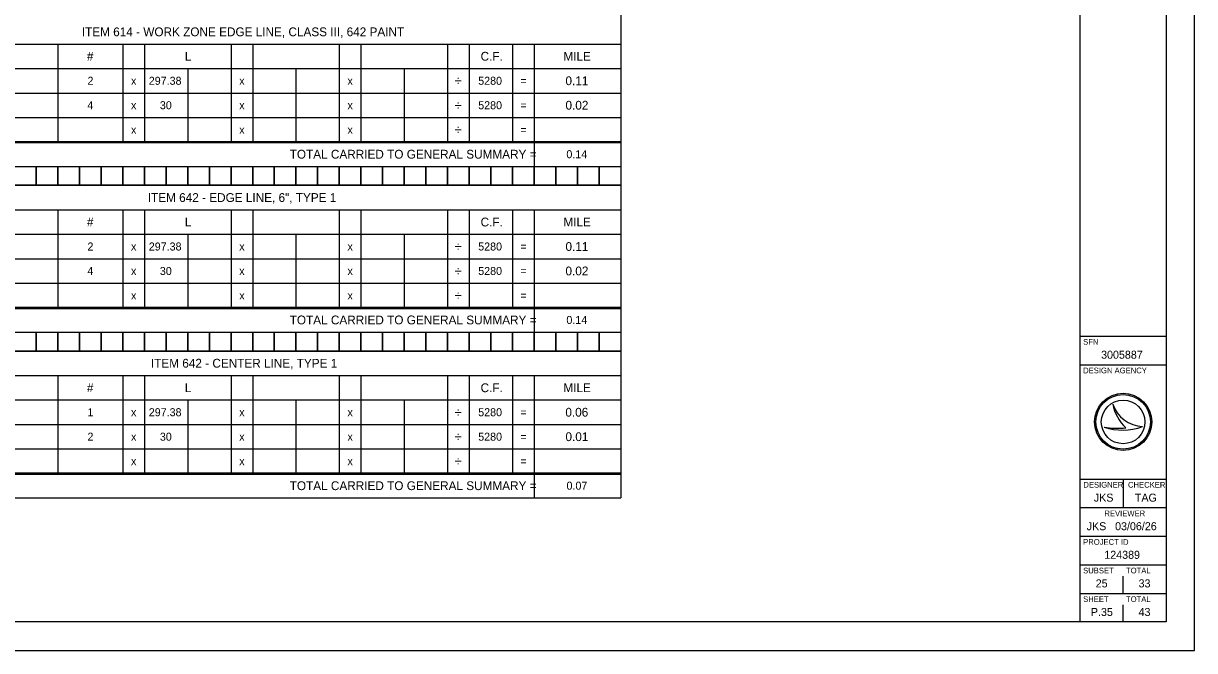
# Model space of a CAD drawing. Extents: x 0 to 34, y 0 to 22.
# Drawn here: x 13.51 to 34, y 0 to 10.97 of the extents above; entities that cross this region are included whole.
import ezdxf

# ---------------------------------------------------------------- set-up
doc = ezdxf.new("R2010")
doc.units = 0
for name, color, linetype in [('Default', 7, 'Continuous'), ('SH_Border', 7, 'Continuous'), ('SH_Cut_Line', 7, 'Continuous'), ('SH_Data', 7, 'Continuous')]:
    doc.layers.add(name, color=color, linetype=linetype)

msp = doc.modelspace()

# ---------------------------------------------------------------- linework, layer by layer
at = {"layer": 'Default'}
for p, q in [((23.957, 11.806), (23.957, 8.885)), ((10.698, 10.609), (23.957, 10.609)), ((14.107, 10.609), (14.107, 8.907)), ((15.244, 10.609), (15.244, 8.907)), ((15.622, 10.609), (15.622, 8.907)), ((17.138, 10.609), (17.138, 8.907)), ((17.517, 10.609), (17.517, 8.907)), ((19.032, 10.609), (19.032, 8.907)), ((19.411, 10.609), (19.411, 8.907)), ((20.926, 10.609), (20.926, 8.907)), ((21.305, 10.609), (21.305, 8.907)), ((22.062, 10.609), (22.062, 8.907)), ((22.441, 10.609), (22.441, 8.907)), ((10.698, 10.181), (23.957, 10.181)), ((16.38, 10.181), (16.38, 8.907)), ((18.274, 10.181), (18.274, 8.907)), ((20.168, 10.181), (20.168, 8.907)), ((10.698, 9.753), (23.957, 9.753)), ((10.698, 9.324), (23.957, 9.324)), ((10.698, 8.907), (23.957, 8.907)), ((10.698, 8.885), (23.957, 8.885)), ((22.441, 8.885), (22.441, 8.468)), ((23.957, 8.907), (23.957, 5.986)), ((10.698, 8.468), (23.957, 8.468)), ((10.698, 8.139), (23.957, 8.139)), ((10.698, 7.71), (23.957, 7.71)), ((14.107, 7.71), (14.107, 6.008)), ((15.244, 7.71), (15.244, 6.008)), ((15.622, 7.71), (15.622, 6.008)), ((17.138, 7.71), (17.138, 6.008)), ((17.517, 7.71), (17.517, 6.008)), ((19.032, 7.71), (19.032, 6.008)), ((19.411, 7.71), (19.411, 6.008)), ((20.926, 7.71), (20.926, 6.008)), ((21.305, 7.71), (21.305, 6.008)), ((22.062, 7.71), (22.062, 6.008)), ((22.441, 7.71), (22.441, 6.008)), ((10.698, 7.282), (23.957, 7.282)), ((16.38, 7.282), (16.38, 6.008)), ((18.274, 7.282), (18.274, 6.008)), ((20.168, 7.282), (20.168, 6.008)), ((10.698, 6.854), (23.957, 6.854)), ((10.698, 6.426), (23.957, 6.426)), ((10.698, 6.008), (23.957, 6.008)), ((10.698, 5.986), (23.957, 5.986)), ((22.441, 5.986), (22.441, 5.569)), ((23.957, 6.008), (23.957, 3.088)), ((10.698, 5.569), (23.957, 5.569)), ((10.698, 5.24), (23.957, 5.24)), ((10.698, 4.811), (23.957, 4.811)), ((14.107, 4.811), (14.107, 3.109)), ((15.244, 4.811), (15.244, 3.109)), ((15.622, 4.811), (15.622, 3.109)), ((17.138, 4.811), (17.138, 3.109)), ((17.517, 4.811), (17.517, 3.109)), ((19.032, 4.811), (19.032, 3.109)), ((19.411, 4.811), (19.411, 3.109)), ((20.926, 4.811), (20.926, 3.109)), ((21.305, 4.811), (21.305, 3.109)), ((22.062, 4.811), (22.062, 3.109)), ((22.441, 4.811), (22.441, 3.109)), ((10.698, 4.383), (23.957, 4.383)), ((16.38, 4.383), (16.38, 3.109)), ((18.274, 4.383), (18.274, 3.109)), ((20.168, 4.383), (20.168, 3.109)), ((10.698, 3.955), (23.957, 3.955)), ((10.698, 3.527), (23.957, 3.527)), ((10.698, 3.109), (23.957, 3.109)), ((10.698, 3.088), (23.957, 3.088)), ((22.441, 3.088), (22.441, 2.67)), ((23.957, 3.109), (23.957, 2.67)), ((10.698, 2.67), (23.957, 2.67))]:
    msp.add_line(p, q, dxfattribs=at)
for points in [[(13.35, 8.468), (13.728, 8.468), (13.728, 8.139), (13.35, 8.139)], [(13.728, 8.468), (14.107, 8.468), (14.107, 8.139), (13.728, 8.139)], [(14.107, 8.468), (14.486, 8.468), (14.486, 8.139), (14.107, 8.139)], [(14.486, 8.468), (14.865, 8.468), (14.865, 8.139), (14.486, 8.139)], [(14.865, 8.468), (15.244, 8.468), (15.244, 8.139), (14.865, 8.139)], [(15.244, 8.468), (15.622, 8.468), (15.622, 8.139), (15.244, 8.139)], [(15.622, 8.468), (16.001, 8.468), (16.001, 8.139), (15.622, 8.139)], [(16.001, 8.468), (16.38, 8.468), (16.38, 8.139), (16.001, 8.139)], [(16.38, 8.468), (16.759, 8.468), (16.759, 8.139), (16.38, 8.139)], [(16.759, 8.468), (17.138, 8.468), (17.138, 8.139), (16.759, 8.139)], [(17.138, 8.468), (17.517, 8.468), (17.517, 8.139), (17.138, 8.139)], [(17.517, 8.468), (17.895, 8.468), (17.895, 8.139), (17.517, 8.139)], [(17.895, 8.468), (18.274, 8.468), (18.274, 8.139), (17.895, 8.139)], [(18.274, 8.468), (18.653, 8.468), (18.653, 8.139), (18.274, 8.139)], [(18.653, 8.468), (19.032, 8.468), (19.032, 8.139), (18.653, 8.139)], [(19.032, 8.468), (19.411, 8.468), (19.411, 8.139), (19.032, 8.139)], [(19.411, 8.468), (19.79, 8.468), (19.79, 8.139), (19.411, 8.139)], [(19.79, 8.468), (20.168, 8.468), (20.168, 8.139), (19.79, 8.139)], [(20.168, 8.468), (20.547, 8.468), (20.547, 8.139), (20.168, 8.139)], [(20.547, 8.468), (20.926, 8.468), (20.926, 8.139), (20.547, 8.139)], [(20.926, 8.468), (21.305, 8.468), (21.305, 8.139), (20.926, 8.139)], [(21.305, 8.468), (21.684, 8.468), (21.684, 8.139), (21.305, 8.139)], [(21.684, 8.468), (22.062, 8.468), (22.062, 8.139), (21.684, 8.139)], [(22.062, 8.468), (22.441, 8.468), (22.441, 8.139), (22.062, 8.139)], [(22.441, 8.468), (22.82, 8.468), (22.82, 8.139), (22.441, 8.139)], [(22.82, 8.468), (23.199, 8.468), (23.199, 8.139), (22.82, 8.139)], [(23.199, 8.468), (23.578, 8.468), (23.578, 8.139), (23.199, 8.139)], [(23.578, 8.468), (23.957, 8.468), (23.957, 8.139), (23.578, 8.139)], [(13.35, 5.569), (13.728, 5.569), (13.728, 5.24), (13.35, 5.24)], [(13.728, 5.569), (14.107, 5.569), (14.107, 5.24), (13.728, 5.24)], [(14.107, 5.569), (14.486, 5.569), (14.486, 5.24), (14.107, 5.24)], [(14.486, 5.569), (14.865, 5.569), (14.865, 5.24), (14.486, 5.24)], [(14.865, 5.569), (15.244, 5.569), (15.244, 5.24), (14.865, 5.24)], [(15.244, 5.569), (15.622, 5.569), (15.622, 5.24), (15.244, 5.24)], [(15.622, 5.569), (16.001, 5.569), (16.001, 5.24), (15.622, 5.24)], [(16.001, 5.569), (16.38, 5.569), (16.38, 5.24), (16.001, 5.24)], [(16.38, 5.569), (16.759, 5.569), (16.759, 5.24), (16.38, 5.24)], [(16.759, 5.569), (17.138, 5.569), (17.138, 5.24), (16.759, 5.24)], [(17.138, 5.569), (17.517, 5.569), (17.517, 5.24), (17.138, 5.24)], [(17.517, 5.569), (17.895, 5.569), (17.895, 5.24), (17.517, 5.24)], [(17.895, 5.569), (18.274, 5.569), (18.274, 5.24), (17.895, 5.24)], [(18.274, 5.569), (18.653, 5.569), (18.653, 5.24), (18.274, 5.24)], [(18.653, 5.569), (19.032, 5.569), (19.032, 5.24), (18.653, 5.24)], [(19.032, 5.569), (19.411, 5.569), (19.411, 5.24), (19.032, 5.24)], [(19.411, 5.569), (19.79, 5.569), (19.79, 5.24), (19.411, 5.24)], [(19.79, 5.569), (20.168, 5.569), (20.168, 5.24), (19.79, 5.24)], [(20.168, 5.569), (20.547, 5.569), (20.547, 5.24), (20.168, 5.24)], [(20.547, 5.569), (20.926, 5.569), (20.926, 5.24), (20.547, 5.24)], [(20.926, 5.569), (21.305, 5.569), (21.305, 5.24), (20.926, 5.24)], [(21.305, 5.569), (21.684, 5.569), (21.684, 5.24), (21.305, 5.24)], [(21.684, 5.569), (22.062, 5.569), (22.062, 5.24), (21.684, 5.24)], [(22.062, 5.569), (22.441, 5.569), (22.441, 5.24), (22.062, 5.24)], [(22.441, 5.569), (22.82, 5.569), (22.82, 5.24), (22.441, 5.24)], [(22.82, 5.569), (23.199, 5.569), (23.199, 5.24), (22.82, 5.24)], [(23.199, 5.569), (23.578, 5.569), (23.578, 5.24), (23.199, 5.24)], [(23.578, 5.569), (23.957, 5.569), (23.957, 5.24), (23.578, 5.24)]]:
    msp.add_lwpolyline(points, close=True, dxfattribs=at)
at = {"layer": 'SH_Border'}
for p, q in [((32, 0.5), (32, 21.5)), ((32, 5.5), (33.5, 5.5)), ((32, 5), (33.5, 5)), ((32, 3), (33.5, 3)), ((32.75, 3), (32.75, 2.5)), ((32, 2.5), (33.5, 2.5)), ((32, 2), (33.5, 2)), ((32, 1.5), (33.5, 1.5)), ((32, 1), (33.5, 1))]:
    msp.add_line(p, q, dxfattribs=at)
msp.add_lwpolyline([(1.5, 21.5), (33.5, 21.5), (33.5, 0.5), (1.5, 0.5)], close=True, dxfattribs=at)
at = {"layer": 'SH_Cut_Line'}
msp.add_lwpolyline([(0, 0), (34, 0), (34, 22), (0, 22)], close=True, dxfattribs=at)
at = {"layer": 'SH_Data'}
for p, q in [((32.567, 4.31), (32.567, 4.31)), ((32.417, 3.91), (32.417, 3.91)), ((32.75, 4), (32.75, 4)), ((33.087, 3.919), (33.087, 3.919)), ((32.75, 1), (32.75, 1.3)), ((32.375, 0.675), (32.375, 0.675)), ((32.75, 0.5), (32.75, 0.8))]:
    msp.add_line(p, q, dxfattribs=at)
for radius in [0.5, 0.477, 0.477, 0.382]:
    msp.add_circle((32.75, 4), radius, dxfattribs=at)
for centre, radius, start, end in [((33.116, 4.498), 0.58, 198.9257, 198.9319), ((33.347, 4.47), 0.796, 191.6379, 191.6421), ((33.116, 4.498), 0.58, 198.9319, 267.1657), ((33.347, 4.47), 0.796, 191.6421, 226.0947), ((32.739, 4.87), 1.013, 251.4576, 290.0832), ((32.648, 5.154), 1.266, 259.4964, 259.4995), ((32.739, 4.87), 1.013, 251.4527, 251.4576), ((32.648, 5.154), 1.266, 259.4995, 276.6672)]:
    msp.add_arc(centre, radius, start, end, dxfattribs=at)

# ---------------------------------------------------------------- texts
at = {"layer": 'Default'}
for s, height, p in [('ITEM 614 - WORK ZONE EDGE LINE, CLASS III, 642 PAINT', 0.154, (14.527, 10.746)), ('#', 0.154, (14.617, 10.318)), ('L', 0.154, (16.33, 10.318)), ('C.F.', 0.154, (21.506, 10.318)), ('MILE', 0.154, (22.955, 10.318)), ('0.11', 0.154, (22.991, 9.89)), ('2', 0.14, (14.626, 9.897)), ('x', 0.14, (15.388, 9.897)), ('297.38', 0.14, (15.699, 9.897)), ('x', 0.14, (17.282, 9.897)), ('x', 0.14, (19.176, 9.897)), ('÷', 0.168, (21.053, 9.883)), ('5280', 0.14, (21.464, 9.897)), ('=', 0.14, (22.202, 9.897)), ('4', 0.14, (14.623, 9.469)), ('x', 0.14, (15.388, 9.469)), ('30', 0.14, (15.893, 9.469)), ('x', 0.14, (17.282, 9.469)), ('x', 0.14, (19.176, 9.469)), ('÷', 0.168, (21.053, 9.455)), ('5280', 0.14, (21.464, 9.469)), ('=', 0.14, (22.202, 9.469)), ('0.02', 0.154, (22.991, 9.462)), ('x', 0.14, (15.388, 9.04)), ('x', 0.14, (17.282, 9.04)), ('x', 0.14, (19.176, 9.04)), ('÷', 0.168, (21.053, 9.026)), ('=', 0.14, (22.202, 9.04)), ('TOTAL CARRIED TO GENERAL SUMMARY =', 0.154, (18.165, 8.605)), ('0.14', 0.14, (23.007, 8.612)), ('ITEM 642 - EDGE LINE, 6", TYPE 1', 0.154, (15.681, 7.847)), ('#', 0.154, (14.617, 7.419)), ('L', 0.154, (16.33, 7.419)), ('C.F.', 0.154, (21.506, 7.419)), ('MILE', 0.154, (22.955, 7.419)), ('2', 0.14, (14.626, 6.998)), ('x', 0.14, (15.388, 6.998)), ('297.38', 0.14, (15.699, 6.998)), ('x', 0.14, (17.282, 6.998)), ('x', 0.14, (19.176, 6.998)), ('÷', 0.168, (21.053, 6.984)), ('5280', 0.14, (21.464, 6.998)), ('=', 0.14, (22.202, 6.998)), ('0.11', 0.154, (22.991, 6.991)), ('4', 0.14, (14.623, 6.57)), ('x', 0.14, (15.388, 6.57)), ('30', 0.14, (15.893, 6.57)), ('x', 0.14, (17.282, 6.57)), ('x', 0.14, (19.176, 6.57)), ('÷', 0.168, (21.053, 6.556)), ('5280', 0.14, (21.464, 6.57)), ('=', 0.14, (22.202, 6.57)), ('0.02', 0.154, (22.991, 6.563)), ('x', 0.14, (15.388, 6.141)), ('x', 0.14, (17.282, 6.141)), ('x', 0.14, (19.176, 6.141)), ('÷', 0.168, (21.053, 6.127)), ('=', 0.14, (22.202, 6.141)), ('TOTAL CARRIED TO GENERAL SUMMARY =', 0.154, (18.165, 5.706)), ('0.14', 0.14, (23.007, 5.713)), ('ITEM 642 - CENTER LINE, TYPE 1', 0.154, (15.736, 4.949)), ('#', 0.154, (14.617, 4.52)), ('L', 0.154, (16.33, 4.52)), ('C.F.', 0.154, (21.506, 4.52)), ('MILE', 0.154, (22.955, 4.52)), ('1', 0.14, (14.626, 4.099)), ('x', 0.14, (15.388, 4.099)), ('297.38', 0.14, (15.699, 4.099)), ('x', 0.14, (17.282, 4.099)), ('x', 0.14, (19.176, 4.099)), ('÷', 0.168, (21.053, 4.085)), ('5280', 0.14, (21.464, 4.099)), ('=', 0.14, (22.202, 4.099)), ('0.06', 0.154, (22.989, 4.092)), ('2', 0.14, (14.626, 3.671)), ('x', 0.14, (15.388, 3.671)), ('30', 0.14, (15.893, 3.671)), ('x', 0.14, (17.282, 3.671)), ('x', 0.14, (19.176, 3.671)), ('÷', 0.168, (21.053, 3.657)), ('5280', 0.14, (21.464, 3.671)), ('=', 0.14, (22.202, 3.671)), ('0.01', 0.154, (22.991, 3.664)), ('x', 0.14, (15.388, 3.243)), ('x', 0.14, (17.282, 3.243)), ('x', 0.14, (19.176, 3.243)), ('÷', 0.168, (21.053, 3.229)), ('=', 0.14, (22.202, 3.243)), ('TOTAL CARRIED TO GENERAL SUMMARY =', 0.154, (18.165, 2.807)), ('0.07', 0.14, (23.009, 2.814))]:
    msp.add_text(s, height=height, dxfattribs=at).set_placement(p)
at = {"layer": 'SH_Data'}
for s, height, p in [('SFN', 0.1, (32.05, 5.35)), ('3005887', 0.14, (32.364, 5.105)), ('DESIGN AGENCY', 0.1, (32.05, 4.85)), ('DESIGNER', 0.1, (32.054, 2.85)), ('CHECKER', 0.1, (32.835, 2.85)), ('JKS', 0.14, (32.237, 2.605)), ('TAG', 0.14, (32.955, 2.605)), ('REVIEWER', 0.1, (32.422, 2.35)), ('JKS', 0.14, (32.112, 2.105)), ('03/06/26', 0.14, (32.609, 2.105)), ('PROJECT ID', 0.1, (32.05, 1.85)), ('124389', 0.14, (32.42, 1.605)), ('SUBSET', 0.1, (32.05, 1.35)), ('TOTAL', 0.1, (32.8, 1.35)), ('25', 0.14, (32.27, 1.105)), ('33', 0.14, (33.02, 1.105)), ('SHEET', 0.1, (32.05, 0.85)), ('TOTAL', 0.1, (32.8, 0.85)), ('P.35', 0.14, (32.185, 0.605)), ('43', 0.14, (33.02, 0.605))]:
    msp.add_text(s, height=height, dxfattribs=at).set_placement(p)

doc.saveas('drawing.dxf')
